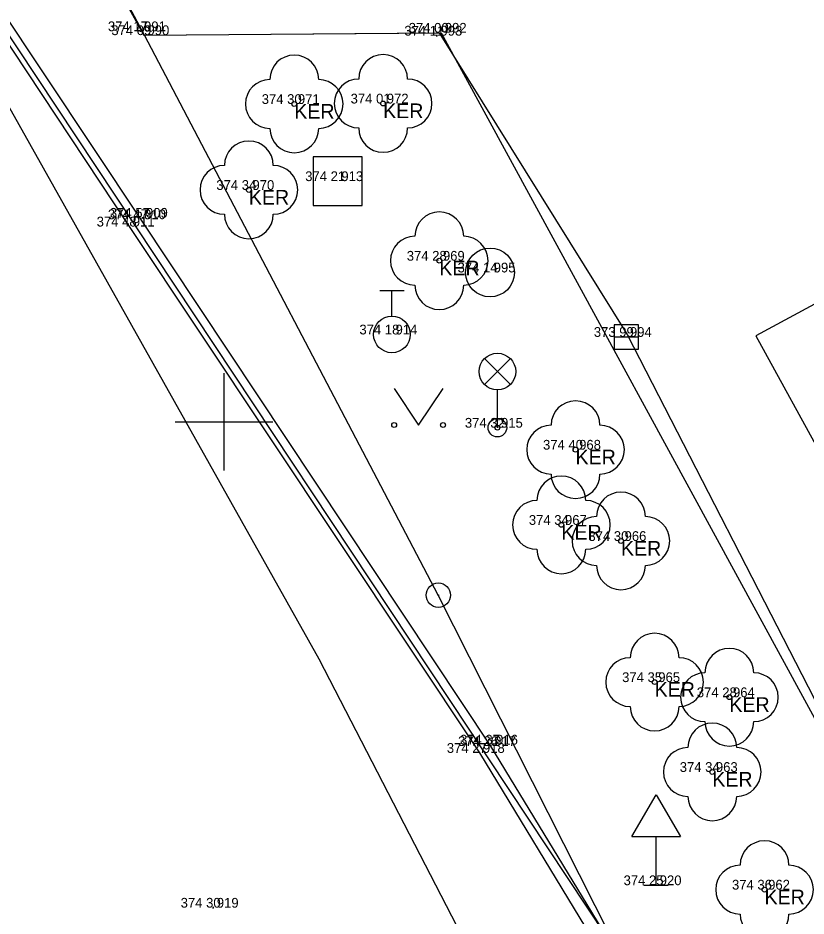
# Model space of a CAD drawing. Extents: x -601196 to -600262, y -1082523 to -1081922.
# Drawn here: x -600554.22 to -600538.08, y -1082160.12 to -1082141.73 of the extents above; entities that cross this region are included whole.
import ezdxf

# ---------------------------------------------------------------- set-up
doc = ezdxf.new("R2010")
doc.units = 0
for name, color, linetype in [('Vrstva 1', 7, 'Continuous'), ('Vrstva 10', 7, 'Continuous'), ('Vrstva 11', 7, 'Continuous'), ('Vrstva 2', 7, 'Continuous'), ('Vrstva 20', 7, 'Continuous'), ('Vrstva 22', 7, 'Continuous'), ('Vrstva 26', 7, 'Continuous'), ('Vrstva 27', 7, 'Continuous'), ('Vrstva 28', 7, 'Continuous'), ('Vrstva 3', 7, 'Continuous'), ('Vrstva 33', 7, 'Continuous'), ('Vrstva 34', 7, 'Continuous'), ('Vrstva 36', 7, 'Continuous'), ('Vrstva 47', 7, 'Continuous'), ('Vrstva 61', 7, 'Continuous'), ('Vrstva 63', 7, 'Continuous')]:
    doc.layers.add(name, color=color, linetype=linetype)

msp = doc.modelspace()

# ---------------------------------------------------------------- linework, layer by layer
at = {"layer": 'Vrstva 1'}
for p, q in [((-600551.71, -1082142), (-600551.71, -1082142)), ((-600545.55, -1082142.03), (-600545.55, -1082142.03)), ((-600551.64, -1082142.08), (-600551.64, -1082142.08)), ((-600545.64, -1082142.09), (-600545.64, -1082142.09)), ((-600548.56, -1082143.49), (-600548.56, -1082143.49)), ((-600546.74, -1082143.48), (-600546.74, -1082143.48)), ((-600547.67, -1082145.07), (-600547.67, -1082145.07)), ((-600549.49, -1082145.25), (-600549.49, -1082145.25)), ((-600551.71, -1082145.85), (-600551.71, -1082145.85)), ((-600551.67, -1082145.82), (-600551.67, -1082145.82)), ((-600551.94, -1082146), (-600551.94, -1082146)), ((-600545.59, -1082146.7), (-600545.59, -1082146.7)), ((-600544.55, -1082146.94), (-600544.55, -1082146.94)), ((-600546.56, -1082148.21), (-600546.56, -1082148.21)), ((-600541.76, -1082148.26), (-600541.76, -1082148.26)), ((-600544.4, -1082150.12), (-600544.4, -1082150.12)), ((-600542.8, -1082150.57), (-600542.8, -1082150.57)), ((-600543.09, -1082152.11), (-600543.09, -1082152.11)), ((-600541.87, -1082152.44), (-600541.87, -1082152.44)), ((-600541.18, -1082155.33), (-600541.18, -1082155.33)), ((-600539.65, -1082155.64), (-600539.65, -1082155.64)), ((-600544.54, -1082156.64), (-600544.54, -1082156.64)), ((-600544.5, -1082156.61), (-600544.5, -1082156.61)), ((-600544.77, -1082156.78), (-600544.77, -1082156.78)), ((-600540, -1082157.17), (-600540, -1082157.17)), ((-600541.15, -1082159.49), (-600541.15, -1082159.49)), ((-600538.93, -1082159.58), (-600538.93, -1082159.58)), ((-600550.22, -1082159.95), (-600550.22, -1082159.95))]:
    msp.add_line(p, q, dxfattribs=at)
at = {"layer": 'Vrstva 10'}
for p, q in [((-600555.57, -1082135.01), (-600551.64, -1082142.08)), ((-600558.86, -1082135.1), (-600551.71, -1082145.85)), ((-600551.64, -1082142.08), (-600545.55, -1082142.03)), ((-600545.55, -1082142.03), (-600536.33, -1082158.97)), ((-600551.71, -1082145.85), (-600544.54, -1082156.64)), ((-600544.54, -1082156.64), (-600534.26, -1082173.54))]:
    msp.add_line(p, q, dxfattribs=at)
at = {"layer": 'Vrstva 11'}
for p, q in [((-600559.08, -1082135.23), (-600551.94, -1082146)), ((-600551.94, -1082146), (-600544.77, -1082156.78)), ((-600544.77, -1082156.78), (-600534.48, -1082173.68))]:
    msp.add_line(p, q, dxfattribs=at)
at = {"layer": 'Vrstva 20'}
for p, q in [((-600551.72, -1082142), (-600551.7, -1082142)), ((-600551.71, -1082141.985), (-600551.71, -1082142)), ((-600551.71, -1082142.015), (-600551.71, -1082142)), ((-600545.65, -1082142.09), (-600545.63, -1082142.09)), ((-600545.64, -1082142.075), (-600545.64, -1082142.09)), ((-600545.64, -1082142.105), (-600545.64, -1082142.09)), ((-600551.68, -1082145.82), (-600551.66, -1082145.82)), ((-600551.67, -1082145.805), (-600551.67, -1082145.82)), ((-600551.67, -1082145.835), (-600551.67, -1082145.82)), ((-600544.51, -1082156.61), (-600544.49, -1082156.61)), ((-600544.5, -1082156.595), (-600544.5, -1082156.61)), ((-600544.5, -1082156.625), (-600544.5, -1082156.61)), ((-600550.23, -1082159.95), (-600550.21, -1082159.95)), ((-600550.22, -1082159.935), (-600550.22, -1082159.95)), ((-600550.22, -1082159.965), (-600550.22, -1082159.95))]:
    msp.add_line(p, q, dxfattribs=at)
at = {"layer": 'Vrstva 22'}
for centre in [(-600548.56, -1082143.49), (-600546.74, -1082143.48), (-600549.49, -1082145.25), (-600545.59, -1082146.7), (-600542.8, -1082150.57), (-600543.09, -1082152.11), (-600541.87, -1082152.44), (-600541.18, -1082155.33), (-600539.65, -1082155.64), (-600540, -1082157.17), (-600538.93, -1082159.58)]:
    msp.add_circle(centre, 0.05, dxfattribs=at)
for centre, start, end in [((-600548.56, -1082142.99), 0, 180), ((-600546.74, -1082142.98), 0, 180), ((-600549.06, -1082143.49), 90, 270), ((-600548.06, -1082143.49), 270, 90), ((-600547.24, -1082143.48), 90, 270), ((-600546.24, -1082143.48), 270, 90), ((-600548.56, -1082143.99), 180, 0), ((-600546.74, -1082143.98), 180, 0), ((-600549.49, -1082144.75), 0, 180), ((-600549.99, -1082145.25), 90, 270), ((-600548.99, -1082145.25), 270, 90), ((-600545.59, -1082146.2), 0, 180), ((-600549.49, -1082145.75), 180, 0), ((-600546.09, -1082146.7), 90, 270), ((-600545.09, -1082146.7), 270, 90), ((-600545.59, -1082147.2), 180, 0), ((-600542.8, -1082150.07), 0, 180), ((-600543.3, -1082150.57), 90, 270), ((-600542.3, -1082150.57), 270, 90), ((-600543.09, -1082151.61), 0, 180), ((-600542.8, -1082151.07), 180, 0), ((-600541.87, -1082151.94), 0, 180), ((-600543.59, -1082152.11), 90, 270), ((-600542.59, -1082152.11), 270, 90), ((-600542.37, -1082152.44), 90, 270), ((-600541.37, -1082152.44), 270, 90), ((-600543.09, -1082152.61), 180, 0), ((-600541.87, -1082152.94), 180, 0), ((-600541.18, -1082154.83), 0, 180), ((-600539.65, -1082155.14), 0, 180), ((-600541.68, -1082155.33), 90, 270), ((-600540.68, -1082155.33), 270, 90), ((-600540.15, -1082155.64), 90, 270), ((-600539.15, -1082155.64), 270, 90), ((-600541.18, -1082155.83), 180, 0), ((-600540, -1082156.67), 0, 180), ((-600539.65, -1082156.14), 180, 0), ((-600540.5, -1082157.17), 90, 270), ((-600539.5, -1082157.17), 270, 90), ((-600540, -1082157.67), 180, 0), ((-600538.93, -1082159.08), 0, 180), ((-600539.43, -1082159.58), 90, 270), ((-600538.43, -1082159.58), 270, 90), ((-600538.93, -1082160.08), 180, 0)]:
    msp.add_arc(centre, 0.5, start, end, dxfattribs=at)
at = {"layer": 'Vrstva 26'}
msp.add_lwpolyline([(-600548.17, -1082145.57), (-600547.17, -1082145.57), (-600547.17, -1082144.57), (-600548.17, -1082144.57)], close=True, dxfattribs=at)
at = {"layer": 'Vrstva 27'}
msp.add_line((-600542.01, -1082148.26), (-600541.51, -1082148.26), dxfattribs=at)
msp.add_lwpolyline([(-600542.01, -1082148.51), (-600541.51, -1082148.51), (-600541.51, -1082148.01), (-600542.01, -1082148.01)], close=True, dxfattribs=at)
msp.add_circle((-600544.55, -1082146.94), 0.5, dxfattribs=at)
at = {"layer": 'Vrstva 28'}
for p, q in [((-600546.81, -1082147.31), (-600546.31, -1082147.31)), ((-600546.56, -1082147.835), (-600546.56, -1082147.31))]:
    msp.add_line(p, q, dxfattribs=at)
msp.add_circle((-600546.56, -1082148.21), 0.375, dxfattribs=at)
at = {"layer": 'Vrstva 33'}
for p, q in [((-600544.665, -1082148.705), (-600544.135, -1082149.235)), ((-600544.665, -1082149.235), (-600544.135, -1082148.705)), ((-600544.4, -1082150.12), (-600544.4, -1082149.345))]:
    msp.add_line(p, q, dxfattribs=at)
for centre, radius in [((-600544.4, -1082148.97), 0.375), ((-600544.4, -1082150.12), 0.19), ((-600544.4, -1082150.12), 0.05)]:
    msp.add_circle(centre, radius, dxfattribs=at)
at = {"layer": 'Vrstva 34'}
for p, q in [((-600541.65, -1082158.49), (-600541.15, -1082157.64)), ((-600541.15, -1082157.64), (-600540.65, -1082158.49)), ((-600541.65, -1082158.49), (-600540.65, -1082158.49)), ((-600541.15, -1082159.49), (-600541.15, -1082158.49)), ((-600541.4, -1082159.49), (-600540.9, -1082159.49))]:
    msp.add_line(p, q, dxfattribs=at)
at = {"layer": 'Vrstva 36'}
for p, q in [((-600546.513, -1082149.315), (-600546.013, -1082150.065)), ((-600546.013, -1082150.065), (-600545.513, -1082149.315))]:
    msp.add_line(p, q, dxfattribs=at)
for centre in [(-600546.513, -1082150.065), (-600545.513, -1082150.065)]:
    msp.add_circle(centre, 0.05, dxfattribs=at)
at = {"layer": 'Vrstva 47'}
for p, q in [((-600551.63, -1082142.08), (-600562.82, -1082120.81)), ((-600551.63, -1082142.08), (-600560.45, -1082126.17)), ((-600548.05, -1082154.86), (-600559.86, -1082133.86)), ((-600559.86, -1082133.86), (-600541.81, -1082161.08)), ((-600551.63, -1082142.08), (-600545.59, -1082142.03)), ((-600545.59, -1082142.03), (-600541.74, -1082148.21)), ((-600545.61, -1082153.55), (-600551.63, -1082142.08)), ((-600534.6, -1082145.8), (-600539.11, -1082148.24)), ((-600541.74, -1082148.21), (-600534.49, -1082162.35)), ((-600539.11, -1082148.24), (-600532.64, -1082160.04)), ((-600541.81, -1082161.08), (-600545.61, -1082153.55)), ((-600530.41, -1082188.99), (-600548.05, -1082154.86))]:
    msp.add_line(p, q, dxfattribs=at)
for radius in [0.25, 0.005]:
    msp.add_circle((-600545.61, -1082153.55), radius, dxfattribs=at)
at = {"layer": 'Vrstva 61'}
for p, q in [((-600550, -1082149), (-600550, -1082151)), ((-600550, -1082149), (-600550, -1082151)), ((-600550, -1082149), (-600550, -1082151)), ((-600551, -1082150), (-600549, -1082150)), ((-600551, -1082150), (-600549, -1082150)), ((-600551, -1082150), (-600549, -1082150))]:
    msp.add_line(p, q, dxfattribs=at)

# ---------------------------------------------------------------- texts
at = {"layer": 'Vrstva 2'}
for s, p in [(' 991', (-600551.71, -1082142)), (' 992', (-600545.55, -1082142.03)), (' 990', (-600551.64, -1082142.08)), (' 993', (-600545.64, -1082142.09)), (' 971', (-600548.56, -1082143.49)), (' 972', (-600546.74, -1082143.48)), (' 913', (-600547.67, -1082145.07)), (' 970', (-600549.49, -1082145.25)), (' 910', (-600551.71, -1082145.85)), (' 909', (-600551.67, -1082145.82)), (' 911', (-600551.94, -1082146)), (' 969', (-600545.59, -1082146.7)), (' 995', (-600544.55, -1082146.94)), (' 914', (-600546.56, -1082148.21)), (' 994', (-600541.76, -1082148.26)), (' 915', (-600544.4, -1082150.12)), (' 968', (-600542.8, -1082150.57)), (' 967', (-600543.09, -1082152.11)), (' 966', (-600541.87, -1082152.44)), (' 965', (-600541.18, -1082155.33)), (' 964', (-600539.65, -1082155.64)), (' 917', (-600544.54, -1082156.64)), (' 916', (-600544.5, -1082156.61)), (' 918', (-600544.77, -1082156.78)), (' 963', (-600540, -1082157.17)), (' 920', (-600541.15, -1082159.49)), (' 962', (-600538.93, -1082159.58)), (' 919', (-600550.22, -1082159.95))]:
    msp.add_text(s, height=0.2, dxfattribs=at).set_placement(p)
at = {"layer": 'Vrstva 3'}
for s, p in [('374 17 ', (-600552.376, -1082142)), ('374 00 ', (-600546.216, -1082142.03)), ('374 09 ', (-600552.306, -1082142.08)), ('374 11 ', (-600546.306, -1082142.09)), ('374 30 ', (-600549.226, -1082143.49)), ('374 01 ', (-600547.406, -1082143.48)), ('374 21 ', (-600548.336, -1082145.07)), ('374 34 ', (-600550.156, -1082145.25)), ('374 47 ', (-600552.376, -1082145.85)), ('374 57 ', (-600552.336, -1082145.82)), ('374 48 ', (-600552.606, -1082146)), ('374 28 ', (-600546.256, -1082146.7)), ('374 14 ', (-600545.216, -1082146.94)), ('374 18 ', (-600547.226, -1082148.21)), ('373 99 ', (-600542.426, -1082148.26)), ('374 32 ', (-600545.066, -1082150.12)), ('374 40 ', (-600543.466, -1082150.57)), ('374 34 ', (-600543.756, -1082152.11)), ('374 30 ', (-600542.536, -1082152.44)), ('374 35 ', (-600541.846, -1082155.33)), ('374 28 ', (-600540.316, -1082155.64)), ('374 26 ', (-600545.206, -1082156.64)), ('374 37 ', (-600545.166, -1082156.61)), ('374 27 ', (-600545.436, -1082156.78)), ('374 34 ', (-600540.666, -1082157.17)), ('374 25 ', (-600541.816, -1082159.49)), ('374 36 ', (-600539.596, -1082159.58)), ('374 30 ', (-600550.886, -1082159.95))]:
    msp.add_text(s, height=0.2, dxfattribs=at).set_placement(p)
at = {"layer": 'Vrstva 63'}
for p in [(-600548.56, -1082143.79), (-600546.74, -1082143.78), (-600549.49, -1082145.55), (-600545.59, -1082147), (-600542.8, -1082150.87), (-600543.09, -1082152.41), (-600541.87, -1082152.74), (-600541.18, -1082155.63), (-600539.65, -1082155.94), (-600540, -1082157.47), (-600538.93, -1082159.88)]:
    msp.add_text('KER', height=0.3, dxfattribs=at).set_placement(p)

doc.saveas('drawing.dxf')
